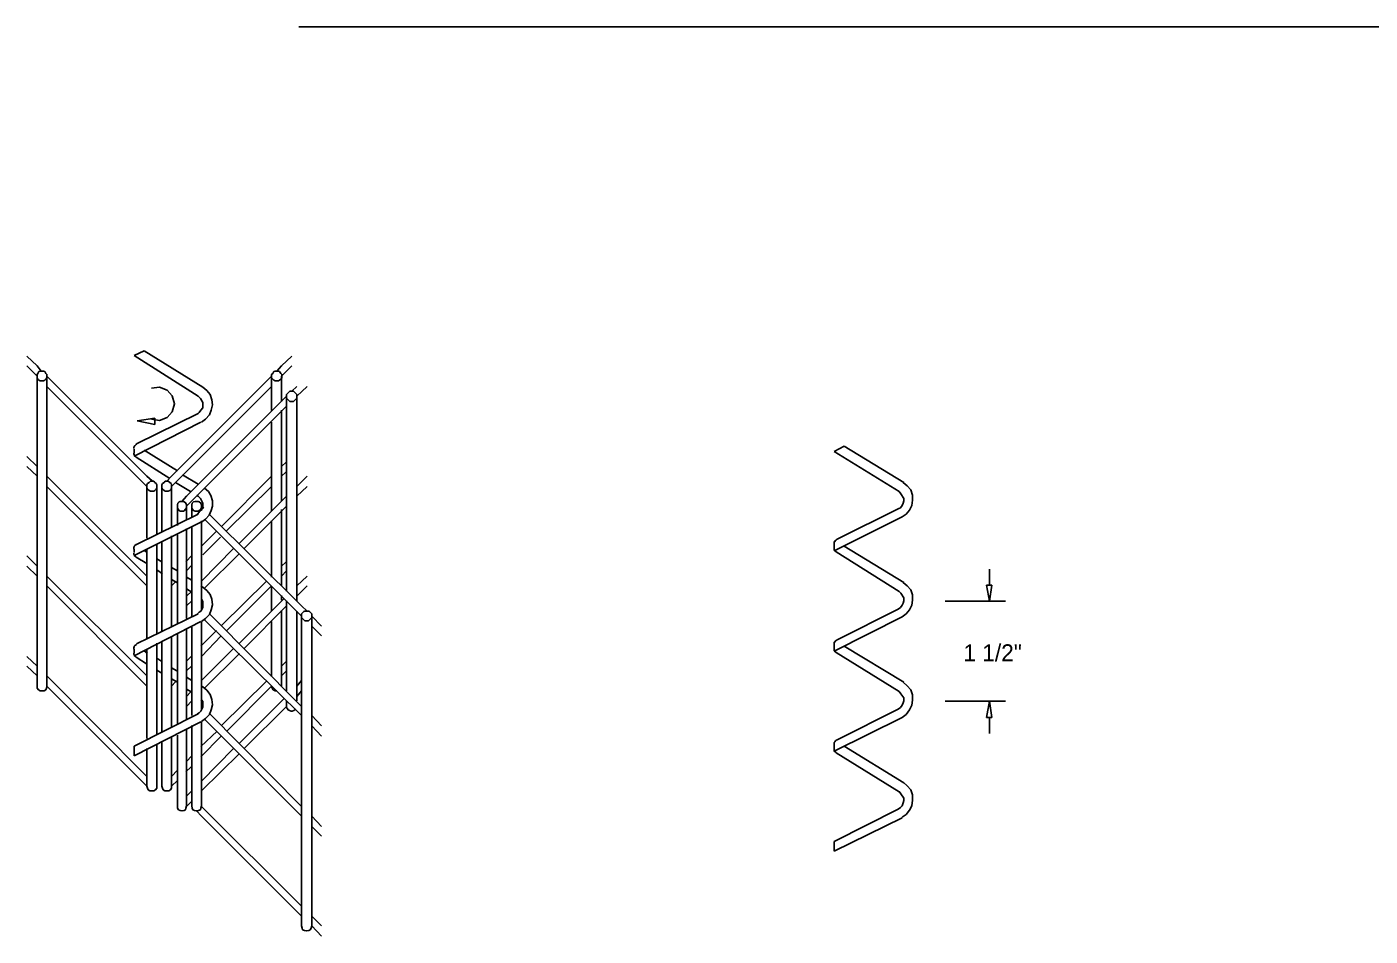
# Model space of a CAD drawing. Extents: x 3 to 3592, y -602 to 1171.
# Drawn here: x 1790.3 to 2027.8, y 837.3 to 998.1 of the extents above; entities that cross this region are included whole.
import ezdxf

# ---------------------------------------------------------------- set-up
doc = ezdxf.new("R2010")
doc.units = 0
for name, color, linetype in [('3', 7, 'Continuous'), ('H', 7, 'Continuous'), ('P', 7, 'Continuous')]:
    doc.layers.add(name, color=color, linetype=linetype)

msp = doc.modelspace()

# ---------------------------------------------------------------- linework, layer by layer
at = {"layer": '3'}
msp.add_line((1838.37, 998.15), (2139.16, 998.15), dxfattribs=at)
at = {"layer": 'H'}
for p, q in [((1812.93, 928.92), (1809.79, 928.42)), ((1812.93, 927.81), (1812.93, 928.92)), ((1809.79, 928.42), (1812.93, 927.81)), ((1960, 899.36), (1960.91, 899.36)), ((1960.51, 896.52), (1960, 899.36)), ((1960.91, 899.36), (1960.51, 896.52)), ((1960.51, 878.84), (1960, 875.99)), ((1960.91, 875.99), (1960.51, 878.84)), ((1960, 875.99), (1960.91, 875.99))]:
    msp.add_line(p, q, dxfattribs=at)
at = {"layer": 'P'}
for points in [[(1809.28, 940), (1811, 940.81)], [(1821.37, 934.41), (1811, 940.81)], [(1792.11, 938.17), (1790.28, 939.9)], [(1820.55, 932.79), (1809.28, 940)], [(1835.29, 938.17), (1837.12, 939.9)], [(1792.11, 936.34), (1790.28, 938.17)], [(1792.82, 937.26), (1792.11, 938.17)], [(1793.83, 936.34), (1793.83, 936.65), (1793.63, 936.85), (1793.43, 937.15), (1793.22, 937.26), (1792.61, 937.26), (1792.41, 937.15), (1792.21, 936.85), (1792.11, 936.65), (1792.11, 936.04), (1792.21, 935.83), (1792.41, 935.63), (1792.61, 935.53), (1793.22, 935.53), (1793.43, 935.63), (1793.63, 935.83), (1793.83, 936.04), (1793.83, 936.54)], [(1792.11, 883.31), (1792.11, 936.34)], [(1811.51, 918.66), (1793.83, 936.34)], [(1793.83, 883.31), (1793.83, 936.34)], [(1815.88, 918.66), (1833.56, 936.34)], [(1835.39, 936.34), (1835.39, 936.65), (1835.19, 936.85), (1834.98, 937.15), (1834.78, 937.26), (1834.17, 937.26), (1833.97, 937.15), (1833.76, 936.85), (1833.56, 936.65), (1833.56, 936.04), (1833.76, 935.83), (1833.97, 935.63), (1834.17, 935.53), (1834.78, 935.53), (1834.98, 935.63), (1835.19, 935.83), (1835.39, 936.04), (1835.39, 936.54)], [(1833.56, 930.25), (1833.56, 936.34)], [(1834.47, 937.26), (1835.29, 938.17)], [(1835.29, 936.34), (1837.12, 938.17)], [(1835.29, 931.87), (1835.29, 936.34)], [(1811.51, 916.83), (1793.83, 934.51)], [(1812.33, 928.72), (1813.75, 928.52), (1815.07, 929.03), (1815.98, 930.04), (1816.39, 931.46), (1815.98, 932.89), (1815.07, 933.9), (1813.75, 934.41), (1812.33, 934.21)], [(1815.88, 916.83), (1833.56, 934.51)], [(1821.16, 928.21), (1821.88, 928.72), (1822.59, 929.53), (1822.89, 930.35), (1823.09, 931.26), (1822.99, 932.18), (1822.69, 933.09), (1822.08, 933.8), (1821.37, 934.41)], [(1838.03, 932.79), (1838.03, 933.09), (1837.83, 933.29), (1837.62, 933.5), (1837.42, 933.7), (1836.81, 933.7), (1836.61, 933.5), (1836.4, 933.29), (1836.2, 933.09), (1836.2, 932.48), (1836.4, 932.28), (1836.61, 932.07), (1836.81, 931.87), (1837.42, 931.87), (1837.62, 932.07), (1837.83, 932.28), (1838.03, 932.48), (1838.03, 932.99)], [(1837.12, 933.7), (1838.03, 934.51)], [(1838.03, 932.79), (1839.86, 934.51)], [(1818.52, 915.11), (1836.2, 932.79)], [(1820.45, 929.64), (1820.76, 929.94), (1821.06, 930.35), (1821.37, 930.75), (1821.37, 931.16), (1821.37, 931.67), (1820.96, 932.38), (1820.55, 932.79)], [(1836.2, 898.34), (1836.2, 932.79)], [(1838.03, 896.62), (1838.03, 932.79)], [(1809.68, 924.35), (1820.55, 929.74)], [(1818.52, 913.38), (1836.2, 931.06)], [(1835.29, 914.29), (1835.29, 930.35)], [(1809.28, 922.22), (1821.06, 928.21)], [(1833.56, 912.47), (1833.56, 928.21)], [(1809.68, 924.35), (1809.58, 924.25), (1809.38, 924.05), (1809.28, 923.95), (1809.28, 923.84), (1809.18, 923.74), (1809.18, 923.54)], [(1792.11, 920.39), (1790.28, 922.12)], [(1809.18, 922.73), (1809.18, 922.52), (1809.28, 922.52), (1809.28, 922.32), (1809.48, 922.12), (1809.58, 922.02)], [(1809.28, 922.73), (1809.28, 923.44)], [(1815.58, 918.26), (1809.58, 922.02)], [(1816.9, 919.58), (1811, 923.23)], [(1933.07, 923.04), (1934.8, 923.95)], [(1944.55, 915.92), (1933.07, 923.04)], [(1945.37, 917.55), (1934.8, 923.95)], [(1792.11, 918.66), (1790.28, 920.39)], [(1835.29, 920.39), (1836.2, 921.2)], [(1835.29, 918.66), (1836.1, 919.37)], [(1811.51, 900.98), (1793.83, 918.66)], [(1811.51, 918.66), (1812.43, 917.85)], [(1813.24, 916.83), (1813.24, 917.14), (1813.14, 917.34), (1812.93, 917.55), (1812.73, 917.75), (1812.12, 917.75), (1811.92, 917.55), (1811.61, 917.34), (1811.51, 917.14), (1811.51, 916.53), (1811.61, 916.33), (1811.92, 916.12), (1812.12, 916.02), (1812.73, 916.02), (1812.93, 916.12), (1813.14, 916.33), (1813.24, 916.53), (1813.24, 917.04)], [(1815.88, 916.83), (1815.88, 917.14), (1815.78, 917.34), (1815.58, 917.55), (1815.27, 917.75), (1814.76, 917.75), (1814.56, 917.55), (1814.26, 917.34), (1814.15, 917.14), (1814.15, 916.53), (1814.26, 916.33), (1814.56, 916.12), (1814.76, 916.02), (1815.27, 916.02), (1815.58, 916.12), (1815.78, 916.33), (1815.88, 916.53), (1815.88, 917.04)], [(1815.88, 918.66), (1815.07, 917.85)], [(1819.23, 915.92), (1816.59, 917.55)], [(1820.55, 917.24), (1817.81, 918.87)], [(1824.62, 909.72), (1833.56, 918.66)], [(1838.03, 916.83), (1839.86, 918.66)], [(1945.06, 911.45), (1945.77, 911.96), (1946.38, 912.67), (1946.79, 913.48), (1946.89, 914.4), (1946.89, 915.31), (1946.59, 916.23), (1945.98, 916.94), (1945.27, 917.55)], [(1811.51, 899.26), (1793.83, 916.83)], [(1811.51, 916.83), (1811.51, 907.69)], [(1813.24, 916.83), (1813.24, 908.3)], [(1814.15, 916.83), (1814.15, 908.81)], [(1815.88, 916.83), (1815.88, 909.62)], [(1818.52, 915.11), (1817.71, 914.19)], [(1820.55, 915.11), (1820.25, 915.21)], [(1820.45, 911.96), (1820.76, 912.26), (1821.06, 912.57), (1821.37, 913.07), (1821.37, 913.48), (1821.37, 913.89), (1820.96, 914.7), (1820.55, 915.11)], [(1821.16, 910.53), (1821.88, 911.04), (1822.49, 911.75), (1822.89, 912.57), (1823.09, 913.38), (1823.09, 914.29), (1822.79, 915.21), (1822.38, 915.92), (1821.67, 916.53)], [(1825.53, 908.91), (1833.56, 916.83)], [(1827.87, 906.78), (1836.2, 915.11)], [(1838.03, 915.11), (1839.86, 916.83)], [(1944.35, 912.88), (1944.76, 913.08), (1945.06, 913.48), (1945.27, 913.89), (1945.37, 914.3), (1945.37, 914.7), (1944.86, 915.52), (1944.55, 915.92)], [(1818.52, 913.38), (1818.52, 913.58), (1818.42, 913.89), (1818.01, 914.19), (1817.41, 914.19), (1817.2, 914.09), (1817, 913.89), (1816.9, 913.58), (1816.9, 913.07), (1817, 912.87), (1817.2, 912.57), (1817.41, 912.47), (1818.01, 912.47), (1818.42, 912.87), (1818.52, 913.07), (1818.52, 913.48)], [(1816.9, 913.38), (1816.9, 909.93)], [(1818.52, 913.38), (1818.52, 911.04)], [(1821.16, 913.38), (1821.16, 913.58), (1821.06, 913.89), (1820.76, 914.09), (1820.55, 914.19), (1820.05, 914.19), (1819.74, 914.09), (1819.54, 913.89), (1819.44, 913.58), (1819.44, 913.07), (1819.54, 912.87), (1819.74, 912.57), (1820.05, 912.47), (1820.55, 912.47), (1820.76, 912.57), (1821.06, 912.87), (1821.16, 913.07), (1821.16, 913.48)], [(1819.44, 913.38), (1819.44, 911.35)], [(1821.16, 913.38), (1821.16, 912.57)], [(1821.16, 913.38), (1821.57, 912.97)], [(1828.68, 905.86), (1836.2, 913.38)], [(1835.29, 899.26), (1835.29, 912.77)], [(1933.58, 907.49), (1944.35, 912.88)], [(1809.28, 904.64), (1821.06, 910.53)], [(1809.68, 906.57), (1820.55, 911.96)], [(1821.16, 910.74), (1821.16, 894.89)], [(1821.67, 911.04), (1838.84, 893.87)], [(1822.59, 911.86), (1838.84, 895.7)], [(1833.56, 900.78), (1833.56, 910.74)], [(1933.07, 905.46), (1945.06, 911.45)], [(1815.88, 908.1), (1815.88, 892.15)], [(1816.9, 908.3), (1816.9, 892.45)], [(1818.52, 909.42), (1818.52, 893.47)], [(1819.44, 909.62), (1819.44, 893.87)], [(1821.16, 906.27), (1823.81, 908.91)], [(1821.37, 904.74), (1824.52, 907.89)], [(1933.58, 907.49), (1933.38, 907.39), (1933.28, 907.29), (1933.17, 907.08), (1933.07, 907.08), (1933.07, 906.88), (1933.07, 906.68)], [(1809.68, 906.57), (1809.58, 906.57), (1809.38, 906.37), (1809.28, 906.27), (1809.28, 906.17), (1809.18, 906.06), (1809.18, 905.76)], [(1809.28, 905.15), (1809.28, 905.76)], [(1811.51, 905.15), (1811, 905.56)], [(1811.51, 905.76), (1811.51, 889.81)], [(1813.24, 906.57), (1813.24, 890.72)], [(1814.15, 907.18), (1814.15, 891.13)], [(1821.16, 900.07), (1826.85, 905.86)], [(1933.07, 905.86), (1933.07, 906.68)], [(1933.07, 905.97), (1933.07, 905.76), (1933.07, 905.66), (1933.07, 905.56), (1933.38, 905.26), (1933.48, 905.26)], [(1944.55, 898.24), (1933.38, 905.26)], [(1945.37, 899.87), (1934.8, 906.27)], [(1792.11, 902.71), (1790.28, 904.54)], [(1809.18, 905.05), (1809.18, 904.85), (1809.28, 904.74), (1809.28, 904.64), (1809.48, 904.44), (1809.58, 904.34)], [(1811.51, 903.22), (1809.58, 904.34)], [(1814.15, 903.52), (1813.24, 904.03)], [(1818.42, 903.52), (1819.44, 904.64)], [(1818.52, 901.9), (1819.44, 902.91)], [(1821.67, 898.85), (1827.87, 904.95)], [(1835.29, 902.71), (1836.1, 903.42)], [(1792.11, 900.98), (1790.28, 902.71)], [(1811.51, 883.31), (1793.83, 900.98)], [(1814.26, 901.39), (1813.24, 902.1)], [(1816.9, 901.9), (1815.88, 902.51)], [(1816.9, 899.77), (1815.88, 900.37)], [(1819.44, 900.27), (1818.52, 900.78)], [(1835.29, 900.98), (1836.2, 901.9)], [(1838.03, 899.26), (1839.86, 900.98)], [(1960.51, 899.36), (1960.51, 902.21)], [(1811.51, 881.48), (1793.83, 899.26)], [(1815.88, 899.26), (1816.59, 899.97)], [(1819.44, 898.14), (1818.52, 898.75)], [(1818.52, 897.43), (1819.44, 898.34)], [(1821.37, 899.05), (1821.06, 899.26)], [(1821.16, 892.96), (1821.88, 893.47), (1822.59, 894.18), (1822.89, 894.99), (1823.09, 895.9), (1822.99, 896.92), (1822.69, 897.73), (1822.08, 898.44), (1821.37, 899.05)], [(1824.72, 892.25), (1832.65, 900.07)], [(1825.63, 891.33), (1833.56, 899.26)], [(1833.56, 894.79), (1833.56, 899.16)], [(1838.03, 897.43), (1839.86, 899.26)], [(1944.35, 895.1), (1944.76, 895.4), (1945.06, 895.81), (1945.27, 896.21), (1945.37, 896.62), (1945.37, 897.13), (1944.86, 897.94), (1944.55, 898.24)], [(1945.06, 893.77), (1945.77, 894.28), (1946.38, 894.99), (1946.79, 895.81), (1946.89, 896.72), (1946.89, 897.64), (1946.59, 898.55), (1945.98, 899.26), (1945.27, 899.87)], [(1818.52, 895.7), (1819.44, 896.62)], [(1820.45, 894.28), (1820.76, 894.58), (1821.06, 894.79), (1821.37, 895.4), (1821.37, 895.8), (1821.37, 896.11), (1821.37, 896.51), (1821.16, 896.92)], [(1821.16, 895.7), (1821.47, 895.5)], [(1827.87, 889.1), (1835.79, 897.02)], [(1828.68, 888.18), (1836.2, 895.7)], [(1835.29, 896.72), (1835.29, 897.53)], [(1836.2, 880.66), (1836.2, 896.62)], [(1839.86, 894.79), (1838.84, 895.7)], [(1952.68, 896.52), (1963.35, 896.52)], [(1809.68, 889), (1820.55, 894.28)], [(1821.67, 893.26), (1838.84, 876.3)], [(1822.59, 894.28), (1838.84, 877.92)], [(1835.29, 883.31), (1835.29, 894.89)], [(1838.03, 879.65), (1838.03, 894.79)], [(1840.67, 893.97), (1840.67, 894.28), (1840.47, 894.48), (1840.27, 894.69), (1840.06, 894.79), (1839.45, 894.79), (1839.25, 894.69), (1839.05, 894.48), (1838.84, 894.28), (1838.84, 893.67), (1839.05, 893.47), (1839.25, 893.26), (1839.45, 893.06), (1840.06, 893.06), (1840.27, 893.26), (1840.47, 893.47), (1840.67, 893.67), (1840.67, 894.08)], [(1838.84, 840.84), (1838.84, 893.87)], [(1840.67, 840.84), (1840.67, 893.87)], [(1840.67, 893.87), (1842.4, 892.15)], [(1933.07, 887.68), (1945.06, 893.77)], [(1933.58, 889.71), (1944.35, 895.1)], [(1809.28, 886.86), (1821.06, 892.96)], [(1818.52, 891.64), (1818.52, 875.58)], [(1819.44, 891.94), (1819.44, 876.3)], [(1821.06, 888.59), (1823.81, 891.33)], [(1821.16, 892.96), (1821.16, 877.31)], [(1833.56, 883.31), (1833.56, 892.96)], [(1840.67, 892.15), (1842.4, 890.42)], [(1809.68, 888.89), (1809.58, 888.79), (1809.38, 888.69), (1809.28, 888.59), (1809.28, 888.49), (1809.18, 888.28), (1809.18, 888.08)], [(1813.24, 889.1), (1813.24, 872.84)], [(1814.15, 889.4), (1814.15, 873.35)], [(1815.88, 890.32), (1815.88, 874.16)], [(1816.9, 890.72), (1816.9, 874.77)], [(1821.16, 886.76), (1824.62, 890.42)], [(1933.58, 889.71), (1933.38, 889.61), (1933.28, 889.51), (1933.17, 889.3), (1933.07, 889.3), (1933.07, 889.1), (1933.07, 888.9)], [(1933.07, 888.19), (1933.07, 889)], [(1945.37, 882.19), (1934.8, 888.59)], [(1792.11, 885.03), (1790.28, 886.76)], [(1809.18, 887.37), (1809.18, 887.17), (1809.28, 887.07), (1809.28, 886.96), (1809.48, 886.76), (1809.58, 886.66)], [(1809.28, 887.37), (1809.28, 888.08)], [(1811.41, 885.44), (1809.58, 886.66)], [(1811.61, 887.27), (1811, 887.78)], [(1811.51, 887.98), (1811.51, 872.23)], [(1814.15, 885.85), (1813.24, 886.46)], [(1818.52, 885.95), (1819.44, 886.86)], [(1821.16, 882.49), (1826.85, 888.18)], [(1821.67, 881.17), (1827.87, 887.27)], [(1933.07, 888.19), (1933.07, 887.98), (1933.07, 887.88), (1933.07, 887.78), (1933.38, 887.48), (1933.48, 887.48)], [(1944.55, 880.57), (1933.38, 887.48)], [(1792.11, 883.31), (1790.28, 885.03)], [(1814.15, 883.81), (1813.24, 884.32)], [(1816.8, 884.22), (1815.88, 884.73)], [(1818.52, 884.22), (1819.44, 885.13)], [(1835.29, 885.03), (1836.2, 885.95)], [(1835.29, 883.31), (1836.2, 884.22)], [(1792.11, 883.31), (1792.11, 881.48)], [(1792.11, 881.48), (1792.11, 881.17), (1792.31, 880.87), (1792.61, 880.66), (1792.92, 880.66), (1793.33, 880.66), (1793.63, 880.87), (1793.73, 881.17), (1793.83, 881.48)], [(1811.51, 865.53), (1793.83, 883.31)], [(1793.83, 883.31), (1793.83, 881.48)], [(1811.51, 863.8), (1793.83, 881.48)], [(1816.9, 882.19), (1815.88, 882.8)], [(1815.88, 881.48), (1816.59, 882.29)], [(1819.44, 882.49), (1818.52, 883.1)], [(1821.37, 881.38), (1821.16, 881.48)], [(1821.16, 875.28), (1821.88, 875.79), (1822.59, 876.5), (1822.89, 877.31), (1823.09, 878.23), (1822.99, 879.14), (1822.69, 880.05), (1822.08, 880.77), (1821.37, 881.38)], [(1824.62, 874.47), (1832.65, 882.39)], [(1825.63, 873.55), (1833.56, 881.48)], [(1833.56, 883.31), (1833.56, 883.2)], [(1833.56, 881.48), (1833.56, 881.38), (1833.86, 880.87), (1834.17, 880.66), (1834.37, 880.66), (1834.47, 880.66)], [(1835.29, 883.31), (1835.29, 881.48)], [(1835.29, 881.48), (1835.39, 881.48)], [(1838.03, 881.48), (1838.84, 882.49)], [(1945.06, 875.99), (1945.77, 876.5), (1946.38, 877.32), (1946.79, 878.13), (1946.89, 879.04), (1946.89, 879.96), (1946.59, 880.87), (1945.98, 881.58), (1945.27, 882.19)], [(1819.44, 880.46), (1818.52, 880.97)], [(1818.52, 879.65), (1819.23, 880.46)], [(1820.45, 876.6), (1820.76, 876.8), (1821.06, 877.11), (1821.37, 877.82), (1821.37, 878.12), (1821.37, 878.53), (1821.37, 878.84), (1821.06, 879.14)], [(1821.16, 880.66), (1821.27, 880.66)], [(1827.87, 871.42), (1835.79, 879.34)], [(1838.03, 879.65), (1838.84, 880.66)], [(1838.03, 879.65), (1838.03, 878.94)], [(1944.35, 877.42), (1944.76, 877.72), (1945.06, 878.13), (1945.27, 878.53), (1945.37, 878.94), (1945.37, 879.45), (1944.86, 880.16), (1944.55, 880.57)], [(1809.28, 870.91), (1820.55, 876.6)], [(1818.52, 877.92), (1819.44, 878.94)], [(1821.16, 877.92), (1821.47, 877.72)], [(1822.49, 876.7), (1838.84, 860.24)], [(1828.68, 870.5), (1836.2, 877.92)], [(1836.2, 878.84), (1836.2, 877.92)], [(1836.2, 878.02), (1836.2, 877.72), (1836.4, 877.51), (1836.51, 877.31), (1836.71, 877.21), (1837.01, 877.11), (1837.22, 877.11), (1837.52, 877.21), (1837.83, 877.41)], [(1933.58, 872.03), (1944.35, 877.42)], [(1952.68, 878.84), (1963.35, 878.84)], [(1809.28, 869.18), (1821.06, 875.18)], [(1819.44, 874.57), (1819.44, 860.24)], [(1821.16, 875.28), (1821.16, 860.24)], [(1821.67, 875.69), (1838.84, 858.52)], [(1840.67, 876.3), (1842.4, 874.47)], [(1840.67, 874.47), (1842.4, 872.64)], [(1933.07, 870), (1945.06, 875.99)], [(1960.51, 875.99), (1960.51, 873.15)], [(1815.88, 872.54), (1815.88, 863.8)], [(1816.9, 872.84), (1816.9, 860.24)], [(1818.52, 873.86), (1818.52, 860.24)], [(1821.06, 870.81), (1823.91, 873.55)], [(1821.06, 868.98), (1824.62, 872.64)], [(1933.58, 872.03), (1933.38, 871.93), (1933.28, 871.83), (1933.17, 871.63), (1933.07, 871.52), (1933.07, 871.42), (1933.07, 871.22)], [(1809.28, 869.18), (1809.28, 870.91)], [(1811.51, 870.5), (1811.51, 863.8)], [(1813.24, 871.22), (1813.24, 863.8)], [(1814.15, 871.72), (1814.15, 863.8)], [(1821.16, 864.71), (1826.85, 870.5)], [(1821.16, 862.99), (1827.87, 869.59)], [(1933.07, 870.51), (1933.07, 871.22)], [(1933.07, 870.51), (1933.07, 870.3), (1933.07, 870.2), (1933.07, 870), (1933.38, 869.8), (1933.48, 869.7)], [(1944.55, 862.79), (1933.38, 869.7)], [(1945.37, 864.41), (1934.8, 870.91)], [(1818.42, 866.34), (1819.34, 867.25)], [(1818.52, 868.17), (1819.44, 869.18)], [(1815.88, 865.53), (1816.9, 866.64)], [(1815.88, 863.8), (1816.9, 864.81)], [(1811.51, 863.8), (1811.61, 863.49), (1811.72, 863.19), (1812.02, 862.99), (1812.43, 862.99), (1812.73, 862.99), (1813.04, 863.19), (1813.24, 863.49), (1813.24, 863.8)], [(1814.15, 863.8), (1814.26, 863.49), (1814.36, 863.19), (1814.66, 862.99), (1815.07, 862.99), (1815.37, 862.99), (1815.68, 863.19), (1815.88, 863.49), (1815.88, 863.8)], [(1818.52, 862.07), (1819.44, 862.99)], [(1944.35, 859.74), (1944.76, 860.04), (1945.06, 860.35), (1945.27, 860.86), (1945.37, 861.26), (1945.37, 861.67), (1944.86, 862.48), (1944.55, 862.89)], [(1945.06, 858.32), (1945.77, 858.82), (1946.38, 859.54), (1946.79, 860.35), (1946.89, 861.36), (1946.89, 862.28), (1946.59, 863.19), (1945.98, 863.9), (1945.27, 864.51)], [(1816.9, 860.34), (1816.9, 859.94), (1817.1, 859.63), (1817.41, 859.53), (1817.71, 859.43), (1818.12, 859.53), (1818.32, 859.63), (1818.42, 859.94), (1818.52, 860.34)], [(1818.52, 860.24), (1819.44, 861.16)], [(1819.44, 860.34), (1819.54, 859.94), (1819.64, 859.63), (1819.95, 859.53), (1820.25, 859.43), (1820.66, 859.53), (1820.96, 859.63), (1821.06, 859.94), (1821.16, 860.34)], [(1821.16, 860.24), (1838.84, 842.56)], [(1821.16, 858.52), (1820.25, 859.43)], [(1821.16, 858.52), (1838.84, 840.84)], [(1840.67, 858.52), (1842.4, 856.69)], [(1933.07, 854.05), (1944.35, 859.74)], [(1933.07, 852.32), (1945.06, 858.21)], [(1840.67, 856.69), (1842.4, 854.96)], [(1933.07, 852.32), (1933.07, 854.05)], [(1838.84, 840.84), (1838.84, 839.11)], [(1838.84, 839.11), (1838.94, 838.7), (1839.05, 838.4), (1839.35, 838.3), (1839.76, 838.2), (1840.16, 838.3), (1840.37, 838.4), (1840.57, 838.7), (1840.67, 839.11)], [(1840.67, 840.84), (1840.67, 839.11)], [(1840.67, 840.84), (1842.4, 839.11)], [(1840.67, 839.11), (1842.4, 837.28)]]:
    msp.add_lwpolyline(points, dxfattribs=at)

# ---------------------------------------------------------------- texts
at = {"layer": '3'}
msp.add_text('1 1/2"', height=3, dxfattribs=at).set_placement((1955.9, 885.91))

doc.saveas('drawing.dxf')
